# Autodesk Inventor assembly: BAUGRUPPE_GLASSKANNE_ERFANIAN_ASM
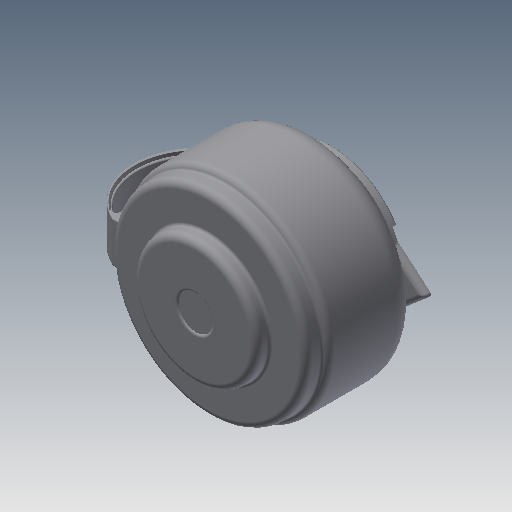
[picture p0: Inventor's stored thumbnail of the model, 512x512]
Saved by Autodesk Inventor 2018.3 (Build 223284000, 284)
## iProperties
Created: 2019-01
Part Number: BAUGRUPPE_GLASSKANNE_ERFANIAN_ASM
Material: Generisch
Document SubType Name: Assembly
Designer: zand
Author: zand
Revision Number: 14LAST_VERSION
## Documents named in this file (4)
- D:\10_CAD-ÜBUNGEN\KAFFEEMASCHINE\Workspaces\Arbeitsbereich\BAUGRUPPE_GLASSKANNE_ERFANIAN_ASM.iam
- D:\10_CAD-ÜBUNGEN\KAFFEEMASCHINE\Workspaces\Arbeitsbereich\GLASSKANNE_ERFANIAN.ipt
- D:\10_CAD-ÜBUNGEN\KAFFEEMASCHINE\Workspaces\Arbeitsbereich\HANDGRIFF_ERFANIAN_AF0.ipt
- D:\10_CAD-ÜBUNGEN\KAFFEEMASCHINE\Workspaces\Arbeitsbereich\GLASSKANNEDECKEL_ERFANIAN_AF0.ipt
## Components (3 placed, 3 different names)
1. Glaskanne
2. Handgriff
3. Glaskannendeckel
